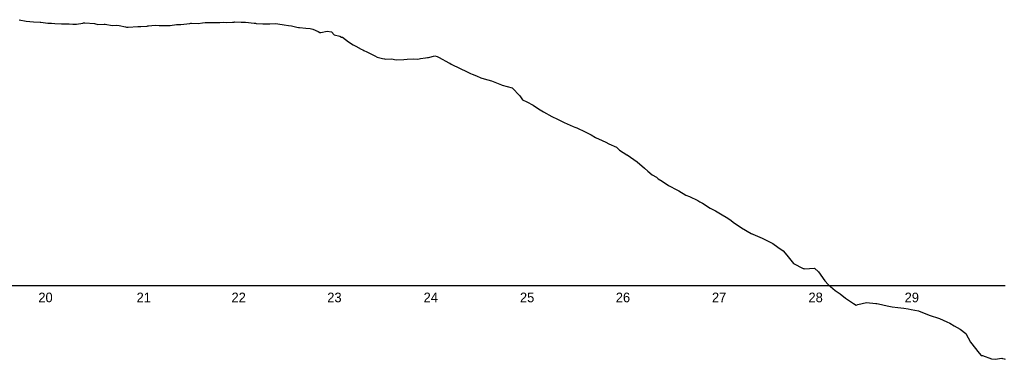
# Model space of a CAD drawing. Extents: x 1778432 to 1784301, y 601022 to 621789.
# Drawn here: x 1781116 to 1782140, y 602962 to 603315 of the extents above; entities that cross this region are included whole.
import ezdxf

# ---------------------------------------------------------------- set-up
doc = ezdxf.new("R2010")
doc.units = 0
for name, color, linetype in [('Exist Profile Cell', 7, 'Continuous'), ('Exist Vertical Profile Ground Line', 7, 'Continuous'), ('Exist Vertical Profile Horizontal Axis Label Major', 7, 'Continuous')]:
    doc.layers.add(name, color=color, linetype=linetype)

msp = doc.modelspace()

# ---------------------------------------------------------------- linework, layer by layer
at = {"layer": 'Exist Profile Cell'}
msp.add_line((1780143, 603039.2), (1782139.9, 603039.2), dxfattribs=at)
at = {"layer": 'Exist Vertical Profile Ground Line'}
msp.add_lwpolyline([(1781115.3, 603315.3), (1781122.5, 603313.7), (1781126.5, 603313.4), (1781130, 603313.1), (1781137, 603312.8), (1781137.7, 603312.7), (1781144.9, 603311.8), (1781148.9, 603311.8), (1781152.3, 603311.5), (1781159.2, 603311.1), (1781160, 603311), (1781167.2, 603310.9), (1781171.2, 603310.8), (1781174.7, 603310.7), (1781181.4, 603311.8), (1781182.1, 603311.9), (1781182.4, 603311.9), (1781183.4, 603311.9), (1781193.6, 603311.4), (1781197, 603310.3), (1781203.7, 603310.5), (1781204.4, 603310.5), (1781204.8, 603310.5), (1781211.9, 603309.1), (1781216, 603309.5), (1781219.3, 603309.3), (1781225.9, 603307.8), (1781226.8, 603307.5), (1781227.2, 603307.6), (1781228.5, 603307.6), (1781238.4, 603308.1), (1781241.7, 603308.3), (1781248.2, 603308.7), (1781249.1, 603308.8), (1781249.6, 603308.9), (1781256.6, 603309.5), (1781260.8, 603309.3), (1781270.4, 603309.2), (1781272, 603309.1), (1781278.9, 603310.2), (1781283.2, 603310.4), (1781286.4, 603310.8), (1781292.6, 603311.5), (1781293.8, 603311.6), (1781294.4, 603311.6), (1781301.3, 603311.4), (1781305.6, 603312), (1781308.7, 603312.3), (1781314.9, 603312.3), (1781316.1, 603312.3), (1781316.8, 603312.4), (1781323.6, 603312.4), (1781328, 603312.7), (1781331, 603312.5), (1781337.1, 603312.8), (1781338.5, 603312.8), (1781339.2, 603312.9), (1781345.9, 603312.6), (1781350.4, 603312.6), (1781359.4, 603311.8), (1781360.8, 603311.6), (1781361.6, 603311.5), (1781368.3, 603310.9), (1781372.8, 603311), (1781375.7, 603311), (1781381.6, 603311.2), (1781384, 603311.1), (1781390.6, 603309.8), (1781395.2, 603309.3), (1781398.1, 603309), (1781403.8, 603307.5), (1781405.5, 603307.1), (1781406.4, 603307.2), (1781413, 603306.5), (1781417.5, 603306), (1781420.4, 603305.5), (1781426.1, 603302.9), (1781427.8, 603302), (1781428.7, 603302), (1781435.3, 603303.5), (1781439.9, 603302.7), (1781442.7, 603299.5), (1781448.3, 603298.1), (1781450.2, 603297), (1781451.1, 603297), (1781457.6, 603292.3), (1781462.3, 603289.3), (1781465.1, 603287.7), (1781470.5, 603284.8), (1781472.5, 603283.9), (1781473.5, 603283.4), (1781476.6, 603281.8), (1781484.7, 603277.7), (1781487.4, 603276.5), (1781492.8, 603275), (1781494.9, 603274.6), (1781495.9, 603274.2), (1781502.3, 603274.6), (1781507.1, 603273.7), (1781515, 603274), (1781518.3, 603274.4), (1781524.7, 603274.7), (1781529.5, 603274.3), (1781532.1, 603275), (1781537.3, 603275.5), (1781539.5, 603275.9), (1781540.7, 603275.9), (1781547, 603277.6), (1781549.6, 603277.1), (1781551.8, 603275.9), (1781561.6, 603270.5), (1781562.6, 603270), (1781564.2, 603269.2), (1781573.5, 603264.4), (1781580, 603261.4), (1781584.3, 603259.3), (1781586.1, 603258.7), (1781590.3, 603256.9), (1781595.1, 603255), (1781598.5, 603254), (1781605.9, 603251.6), (1781616.4, 603247.7), (1781617, 603247.4), (1781627.6, 603244.5), (1781635.5, 603236.2), (1781638.4, 603232.1), (1781642.6, 603230.1), (1781649.2, 603226.5), (1781654.9, 603222.6), (1781660.1, 603219.4), (1781668.7, 603214.7), (1781670.9, 603213.5), (1781672.5, 603212.8), (1781681.7, 603208.6), (1781691, 603204.4), (1781692.5, 603203.7), (1781694.8, 603202.8), (1781703.4, 603198.7), (1781709.5, 603195.5), (1781714.2, 603192.8), (1781720.9, 603189.7), (1781725, 603187.9), (1781727.9, 603186.4), (1781735.8, 603182.7), (1781739.1, 603179.7), (1781746.7, 603175), (1781747, 603174.7), (1781757.5, 603167.5), (1781764.9, 603160.9), (1781768.3, 603158), (1781773.1, 603154.2), (1781777.4, 603151.5), (1781779.1, 603150.1), (1781783.4, 603147.4), (1781790, 603143), (1781799.3, 603138.2), (1781800.8, 603137.4), (1781808, 603133.1), (1781811.6, 603131.6), (1781820.4, 603127.3), (1781822.4, 603126.2), (1781825.4, 603124.5), (1781833.3, 603119.4), (1781838.9, 603116.6), (1781844.1, 603113.4), (1781851.5, 603108.9), (1781854.9, 603106.6), (1781857.3, 603104.8), (1781865.7, 603099.1), (1781875.8, 603093.3), (1781876.6, 603092.8), (1781876.9, 603092.8), (1781877.6, 603092.5), (1781887.4, 603088.3), (1781894.3, 603084.9), (1781898.2, 603082.8), (1781903.7, 603079), (1781909, 603075), (1781912.8, 603070.5), (1781919.9, 603062.1), (1781929.8, 603056.8), (1781930.7, 603056.6), (1781931.3, 603056.5), (1781941.5, 603057.2), (1781945.8, 603053.2), (1781952.3, 603043.8), (1781956, 603040.3), (1781963.2, 603033.8), (1781968.3, 603030.6), (1781974, 603026.1), (1781982.1, 603020.4), (1781984.8, 603018.7), (1781986.8, 603019.2), (1781995.6, 603021.5), (1782005.2, 603020.4), (1782006.5, 603020.3), (1782008.2, 603019.9), (1782017.3, 603018.1), (1782022.3, 603017.1), (1782028.1, 603016.4), (1782034.3, 603015.6), (1782038.9, 603014.8), (1782042.2, 603014.2), (1782049.8, 603012.8), (1782060.7, 603008.4), (1782071.4, 603004.8), (1782079.2, 603001.5), (1782082.2, 603000.1), (1782086.6, 602997.3), (1782093.1, 602993.6), (1782098.8, 602989.1), (1782103.9, 602980.1), (1782112.7, 602968.9), (1782114.7, 602966.5), (1782116.2, 602966.3), (1782125.5, 602963), (1782129.4, 602962.5), (1782136.4, 602963.7), (1782137.1, 602963.3), (1782138.8, 602962.8), (1782139.9, 602962.4)], dxfattribs=at)

# ---------------------------------------------------------------- texts
at = {"layer": 'Exist Vertical Profile Horizontal Axis Label Major'}
for s, p in [('20', (1781135.2, 603021.7)), ('21', (1781237.3, 603021.7)), ('22', (1781335.9, 603021.7)), ('23', (1781435.4, 603021.7)), ('24', (1781535.5, 603021.7)), ('25', (1781635.6, 603021.7)), ('26', (1781735.2, 603021.7)), ('27', (1781835.1, 603021.7)), ('28', (1781935.4, 603021.7)), ('29', (1782035.3, 603021.7))]:
    msp.add_text(s, height=10, dxfattribs=at).set_placement(p)

doc.saveas('drawing.dxf')
